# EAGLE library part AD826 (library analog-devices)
High-Speed, Low-Power Dual Operational Amplifier Source: http://www.analog.com/static/imported-files/data_sheets/AD826.pdf
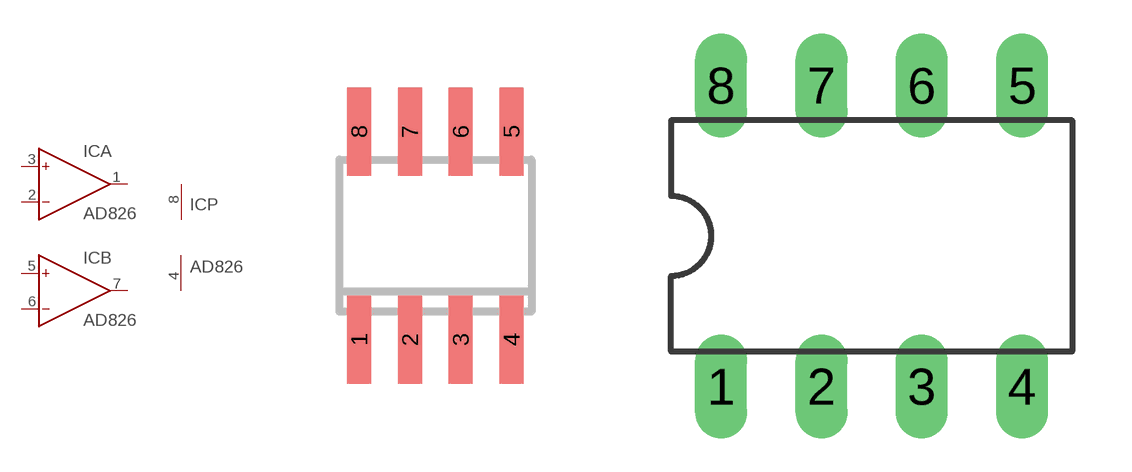
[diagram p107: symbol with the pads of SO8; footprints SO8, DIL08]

Designator prefix IC; gates A=OP B=OP P=PWR+-

## AD826R (MF: ALTERA CORPORATION; MPN: AD826AR; OC_FARNELL: 1651291; OC_NEWARK: 05F7688)  [SO8]
1  A:OUT  out
2  A:IN-  in
3  A:IN+  in
4  P:V-  pwr
5  B:IN+  in
6  B:IN-  in
7  B:OUT  out
8  P:V+  pwr

## AD826N (MF: ALTERA CORPORATION; MPN: AD826ANZ; OC_FARNELL: 1438583; OC_NEWARK: 59K6530)  [DIL08]
Pads as for SO8

## Footprint SO8 (pad centres in mm)
8-Lead Small Outline IC (SO-8) Source: http://www.analog.com/UploadedFiles/Data_Sheets/703465986AD8611_2_0.pdf
smd 0.6 x 2.2: 1 -1.905,-2.6; 2 -0.635,-2.6; 3 0.635,-2.6; 4 1.905,-2.6; 5 1.905,2.6; 6 0.635,2.6; 7 -0.635,2.6; 8 -1.905,2.6

## Footprint DIL08 (pad centres in mm)
Dual In Line Package
drill 0.813 long: 1 -3.81,-3.81; 2 -1.27,-3.81; 3 1.27,-3.81; 4 3.81,-3.81; 5 3.81,3.81; 6 1.27,3.81; 7 -1.27,3.81; 8 -3.81,3.81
